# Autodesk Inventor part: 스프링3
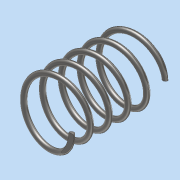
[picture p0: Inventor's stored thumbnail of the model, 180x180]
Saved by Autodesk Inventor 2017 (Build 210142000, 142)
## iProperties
Part Number: 스프링3
Material: 강철, 연강
Document SubType Name: Modeling
Designer: MRC
Density: 7.85 g/cm^3
Appearance: 반연마
Mass: 8.42324 g
Surface Area: 21.7217 cm^2
Volume: 1.07302 cm^3
Author: MRC
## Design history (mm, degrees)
sketch "스케치1"
  geometry: L1 (0, 0)-(0, 36.411); L2 (0, 36.411)-(11, 36.411); L3 (0, 0)-(11, 0); C1 r 1 at (11, 0)
  constraints: 6 end point, 2 horizontal, 1 centre point, 1 coincident, 1 vertical
  dimensions: "d0" = 36.4112 distance of L1.start L1.end (derived); "d2" = 22 diameter of L3.end L1; "d3" = 2 diameter of C1; "d4" = 22 diameter of L2.end L1
feature "코일1" pitch "d5" = 10; turns "d7" = 5; dims "d6" = 36.4112 (= d0), "d8" = 0, angle "d9" = 90 deg, angle "d10" = 90 deg, "d11" = 0, "d12" = 0
sketch "스케치2"
  geometry: L1 (-13.313, 0)-(15.035, 0); L2 (15.035, 0)-(15.035, 36.411); L3 (15.035, 36.411)-(-13.313, 36.411); L4 (-13.313, 36.411)-(-13.313, 0); 1 further point
  constraints: 8 end point, 2 parallel, 1 horizontal, 1 perpendicular
  dimensions: "d13" = 36.4112 distance of L1.end L2.end (= d0)
extrude "돌출1" sketch "스케치2" stored distance "d14" = 0; taper "d15" = 0 deg
node "솔리드1"
